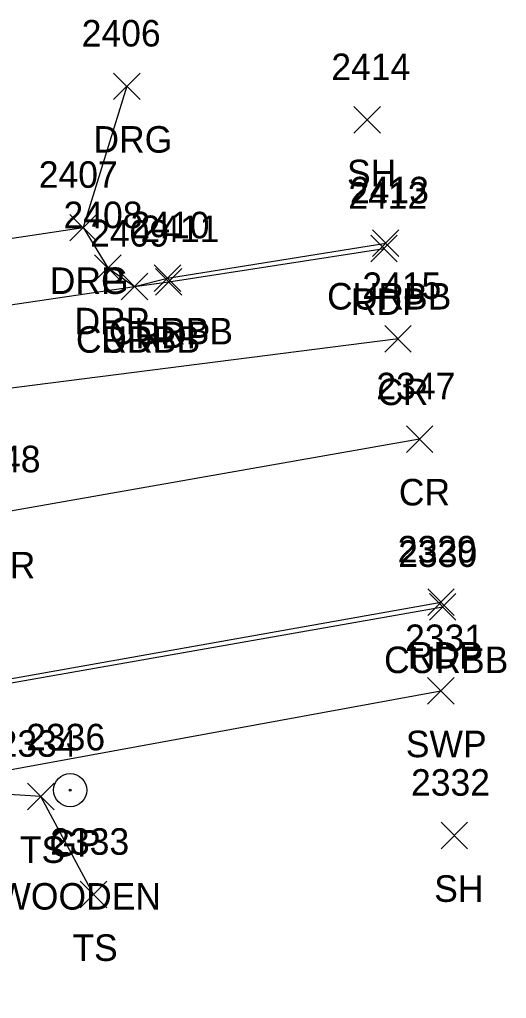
# Model space of a CAD drawing. Extents: x 1769141 to 1770817, y 735471 to 742405.
# Drawn here: x 1770392.1 to 1770428.8, y 741112.2 to 741186 of the extents above; entities that cross this region are included whole.
import ezdxf

# ---------------------------------------------------------------- set-up
doc = ezdxf.new("R2010")
doc.units = 0
for name, color, linetype in [('L_A', 7, 'Continuous'), ('L_I', 7, 'Continuous'), ('L_TIC', 7, 'Continuous'), ('LELB', 7, 'Continuous'), ('P_A', 7, 'Continuous'), ('P_I', 7, 'Continuous'), ('P_TIC', 7, 'Continuous'), ('PET', 7, 'Continuous'), ('PRC', 7, 'Continuous'), ('R_A', 7, 'Continuous'), ('R_C', 7, 'Continuous'), ('R_I', 7, 'Continuous'), ('R_TIC', 7, 'Continuous'), ('RC', 7, 'Continuous'), ('RDG', 7, 'Continuous'), ('RDP', 7, 'Continuous'), ('RGP', 7, 'Continuous'), ('RSW', 7, 'Continuous')]:
    doc.layers.add(name, color=color, linetype=linetype)

msp = doc.modelspace()

# ---------------------------------------------------------------- linework, layer by layer
at = {"layer": 'L_TIC'}
for points in [[(1770417.327, 741177.457), (1770419.327, 741179.457)], [(1770419.327, 741177.457), (1770417.327, 741179.457)], [(1770392.749, 741126.462), (1770394.749, 741128.462)], [(1770394.749, 741126.462), (1770392.749, 741128.462)], [(1770423.898, 741123.527), (1770425.898, 741125.527)], [(1770425.898, 741123.527), (1770423.898, 741125.527)], [(1770396.71, 741119.075), (1770398.71, 741121.075)], [(1770398.71, 741119.075), (1770396.71, 741121.075)]]:
    msp.add_lwpolyline(points, dxfattribs=at)
at = {"layer": 'LELB'}
msp.add_lwpolyline([(1770397.71, 741120.075), (1770393.749, 741127.462), (1770388.976, 741127.777), (1770374.288, 741123.515)], dxfattribs=at)
at = {"layer": 'P_TIC'}
for points in [[(1770418.604, 741167.76), (1770420.604, 741169.76)], [(1770420.604, 741167.76), (1770418.604, 741169.76)], [(1770399.806, 741164.909), (1770401.806, 741166.909)], [(1770401.806, 741164.909), (1770399.806, 741166.909)], [(1770402.378, 741165.25), (1770404.378, 741167.25)], [(1770404.378, 741165.25), (1770402.378, 741167.25)], [(1770419.662, 741160.961), (1770421.662, 741162.961)], [(1770421.662, 741160.961), (1770419.662, 741162.961)], [(1770421.288, 741153.401), (1770423.288, 741155.401)], [(1770423.288, 741153.401), (1770421.288, 741155.401)], [(1770422.899, 741141.105), (1770424.899, 741143.105)], [(1770424.899, 741141.105), (1770422.899, 741143.105)]]:
    msp.add_lwpolyline(points, dxfattribs=at)
at = {"layer": 'PET'}
for points in [[(1770275.19, 741166.437), (1770275.977, 741155.599), (1770278.489, 741153.762), (1770283.376, 741153.643), (1770290.834, 741150.945), (1770293.216, 741150.928), (1770301.387, 741151.584), (1770330.449, 741154.982), (1770332.291, 741155.308), (1770348.778, 741157.994), (1770362.422, 741159.793), (1770366.418, 741160.492), (1770374.133, 741161.731), (1770375.956, 741162.233), (1770400.806, 741165.909), (1770403.378, 741166.25), (1770419.604, 741168.76)], [(1770267.402, 741112.794), (1770270.791, 741114.659), (1770274.372, 741115.598), (1770279.067, 741116.593), (1770280.95, 741116.863), (1770285.981, 741117.808), (1770287.654, 741118.086), (1770313.467, 741122.626), (1770315.364, 741122.711), (1770327.096, 741124.908), (1770329.296, 741125.38), (1770348.677, 741128.817), (1770381.373, 741134.55), (1770423.899, 741142.105)]]:
    msp.add_lwpolyline(points, dxfattribs=at)
at = {"layer": 'PRC'}
for points in [[(1770420.662, 741161.961), (1770386.961, 741157.659), (1770355.709, 741152.482), (1770322.559, 741147.84), (1770294.064, 741143.832), (1770270.938, 741141.774), (1770254.424, 741140.369)], [(1770422.288, 741154.401), (1770391.031, 741148.9), (1770351.212, 741141.744), (1770324.852, 741137.505), (1770305.015, 741134.401), (1770279.252, 741130.869), (1770261.05, 741126.482)]]:
    msp.add_lwpolyline(points, dxfattribs=at)
at = {"layer": 'R_TIC'}
for points in [[(1770399.217, 741179.988), (1770401.217, 741181.988)], [(1770401.217, 741179.988), (1770399.217, 741181.988)], [(1770395.926, 741169.338), (1770397.926, 741171.338)], [(1770397.926, 741169.338), (1770395.926, 741171.338)], [(1770395.926, 741169.338), (1770397.926, 741171.338)], [(1770397.926, 741169.338), (1770395.926, 741171.338)], [(1770418.731, 741168.167), (1770420.731, 741170.167)], [(1770420.731, 741168.167), (1770418.731, 741170.167)], [(1770397.792, 741166.297), (1770399.792, 741168.297)], [(1770399.792, 741166.297), (1770397.792, 741168.297)], [(1770402.282, 741165.533), (1770404.282, 741167.533)], [(1770404.282, 741165.533), (1770402.282, 741167.533)], [(1770399.806, 741164.909), (1770401.806, 741166.909)], [(1770401.806, 741164.909), (1770399.806, 741166.909)], [(1770399.806, 741164.909), (1770401.806, 741166.909)], [(1770401.806, 741164.909), (1770399.806, 741166.909)], [(1770423.024, 741140.766), (1770425.024, 741142.766)], [(1770425.024, 741140.766), (1770423.024, 741142.766)], [(1770422.885, 741134.428), (1770424.885, 741136.428)], [(1770424.885, 741134.428), (1770422.885, 741136.428)]]:
    msp.add_lwpolyline(points, dxfattribs=at)
at = {"layer": 'RC'}
for points in [[(1770400.806, 741165.909), (1770403.282, 741166.533), (1770419.731, 741169.167)], [(1770327.096, 741124.908), (1770329.309, 741125.136), (1770348.535, 741128.502), (1770381.358, 741134.253), (1770424.024, 741141.766)]]:
    msp.add_lwpolyline(points, dxfattribs=at)
at = {"layer": 'RDG'}
msp.add_lwpolyline([(1770400.217, 741180.988), (1770396.926, 741170.338)], dxfattribs=at)
at = {"layer": 'RDP'}
msp.add_lwpolyline([(1770375.956, 741162.233), (1770381.526, 741168.048), (1770396.926, 741170.338), (1770398.792, 741167.297), (1770400.806, 741165.909)], dxfattribs=at)
at = {"layer": 'RGP'}
msp.add_line((1770395.955, 741127.944), (1770395.955, 741127.944), dxfattribs=at)
for radius in [1.25, 0.0833]:
    msp.add_circle((1770395.955, 741127.944), radius, dxfattribs=at)
at = {"layer": 'RSW'}
msp.add_lwpolyline([(1770293.745, 741112.25), (1770315.627, 741116.109), (1770329.06, 741118.452), (1770346.845, 741121.665), (1770347.607, 741118.02), (1770351.128, 741119.098), (1770350.707, 741122.277), (1770366.412, 741124.952), (1770367.41, 741121.56), (1770370.433, 741121.809), (1770369.828, 741125.643), (1770385.176, 741128.353), (1770423.885, 741135.428)], dxfattribs=at)

# ---------------------------------------------------------------- texts
at = {"layer": 'L_A'}
for s, p in [('SH', (1770416.815, 741173.457)), ('TS', (1770392.159, 741122.462)), ('SH', (1770423.386, 741119.527)), ('TS', (1770396.12, 741115.075))]:
    msp.add_text(s, height=2, dxfattribs=at).set_placement(p)
at = {"layer": 'L_I'}
for s, p in [('2414', (1770415.634, 741181.457)), ('2334', (1770390.489, 741130.462)), ('2332', (1770421.638, 741127.527)), ('2333', (1770394.451, 741123.075))]:
    msp.add_text(s, height=2, dxfattribs=at).set_placement(p)
at = {"layer": 'P_A'}
for s, p in [('RDP', (1770417.092, 741163.76)), ('RDP', (1770400.867, 741161.25)), ('RDP', (1770398.294, 741160.909)), ('CR', (1770419.095, 741156.961)), ('CR', (1770420.721, 741149.401)), ('CR', (1770389.464, 741143.9)), ('RDP', (1770421.387, 741137.105))]:
    msp.add_text(s, height=2, dxfattribs=at).set_placement(p)
at = {"layer": 'P_I'}
for s, p in [('2412', (1770416.911, 741171.76)), ('2411', (1770401.253, 741169.25)), ('2409', (1770397.46, 741168.909)), ('2415', (1770417.969, 741164.961)), ('2347', (1770419.028, 741157.401)), ('2348', (1770387.771, 741151.9)), ('2329', (1770420.631, 741145.105))]:
    msp.add_text(s, height=2, dxfattribs=at).set_placement(p)
at = {"layer": 'R_A'}
for s, p in [('DRG', (1770397.705, 741175.988)), ('DRG', (1770394.414, 741165.338)), ('DRP', (1770394.414, 741165.338)), ('CURBB', (1770415.313, 741164.167)), ('DRP', (1770396.28, 741162.297)), ('CURBB', (1770398.865, 741161.533)), ('CURBB', (1770396.389, 741160.909)), ('DRP', (1770398.294, 741160.909)), ('CURBB', (1770419.606, 741136.766)), ('SWP', (1770421.247, 741130.428)), ('GP', (1770394.388, 741122.944))]:
    msp.add_text(s, height=2, dxfattribs=at).set_placement(p)
at = {"layer": 'R_C'}
msp.add_text('WOODEN', height=2, dxfattribs=at).set_placement((1770390.467, 741118.944))
at = {"layer": 'R_I'}
for s, p in [('2406', (1770396.824, 741183.988)), ('2407', (1770393.587, 741173.338)), ('2407', (1770393.587, 741173.338)), ('2413', (1770417.038, 741172.167)), ('2408', (1770395.454, 741170.297)), ('2410', (1770400.503, 741169.533)), ('2409', (1770397.46, 741168.909)), ('2409', (1770397.46, 741168.909)), ('2330', (1770420.677, 741144.766)), ('2331', (1770421.192, 741138.428)), ('2336', (1770392.64, 741130.944))]:
    msp.add_text(s, height=2, dxfattribs=at).set_placement(p)

doc.saveas('drawing.dxf')
